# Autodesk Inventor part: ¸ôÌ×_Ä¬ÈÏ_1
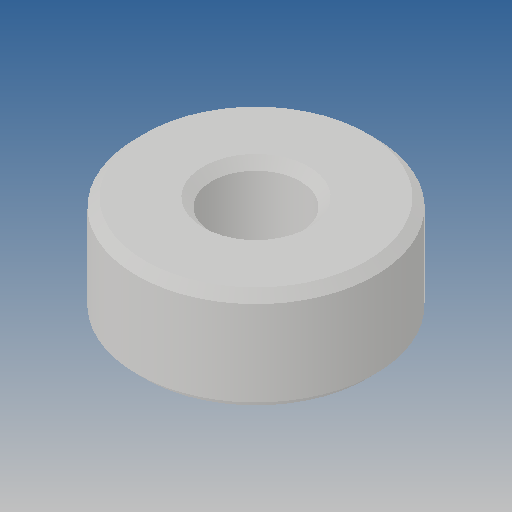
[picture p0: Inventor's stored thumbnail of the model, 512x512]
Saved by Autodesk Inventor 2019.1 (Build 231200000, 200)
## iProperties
Created: 2012-10
Part Number: ¸ôÌ×_Ä¬ÈÏ_1
Material: Ogólny
Document SubType Name: Modeling
Designer: CADENGINEERING4
Density: 1 g/cm^3
Appearance: Domyślna
Author: CADENGINEERING4
Revision Number: ÈÎºÎ
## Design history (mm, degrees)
feature "NONE"
node "Bryła1"
